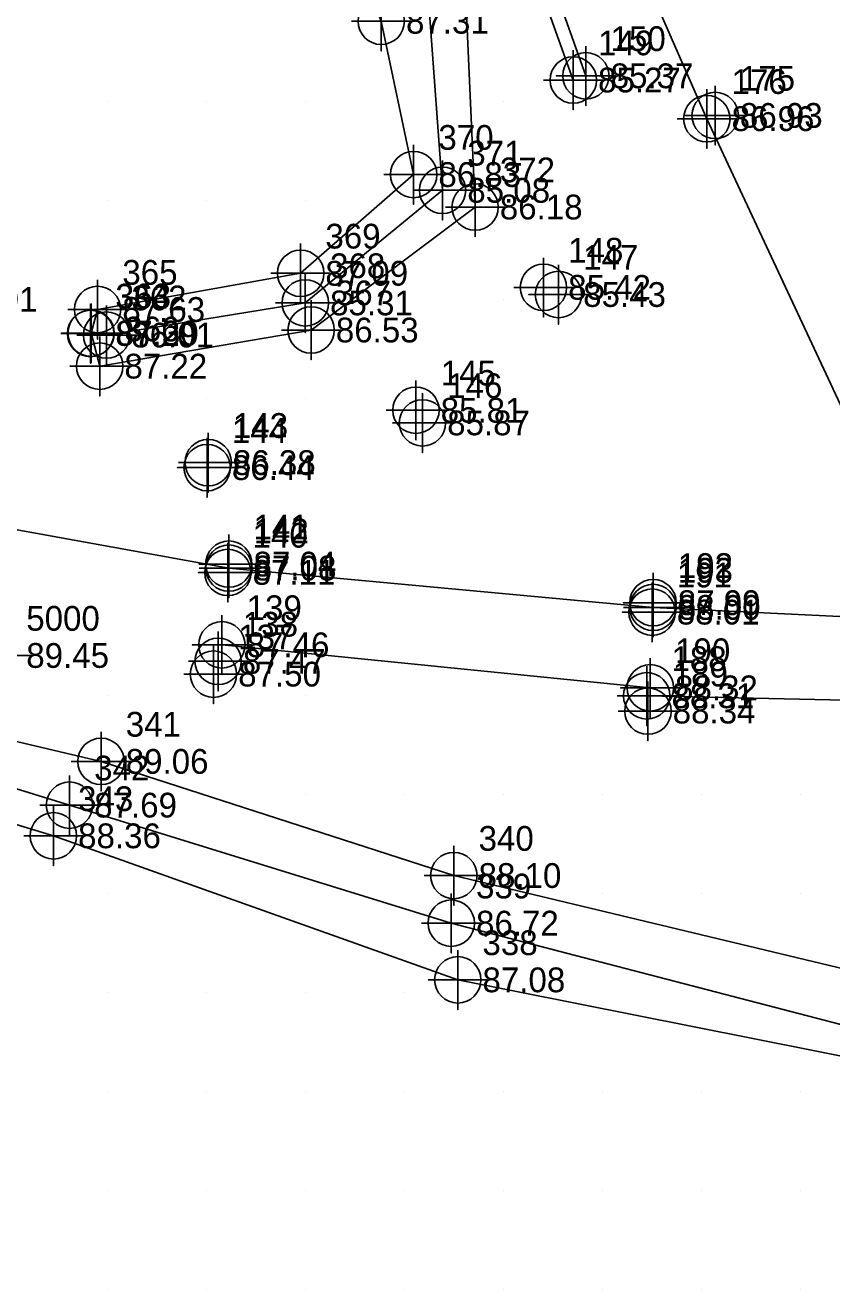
# Model space of a CAD drawing. Extents: x 1988140 to 1988766, y 249950 to 250250.
# Drawn here: x 1988211.7 to 1988293.2, y 249980 to 250107.7 of the extents above; entities that cross this region are included whole.
import ezdxf

# ---------------------------------------------------------------- set-up
doc = ezdxf.new("R2010")
doc.units = 0
for name, color, linetype in [('Exist DTM Breakline', 7, 'Continuous'), ('Exist DTM Breakline Cogo Elevation', 7, 'Continuous'), ('Exist DTM Breakline Cogo Number', 7, 'Continuous'), ('Exist DTM Breakline Cogo Point CELL', 7, 'Continuous'), ('Exist DTM Crownline', 7, 'Continuous'), ('Exist DTM Crownline Cogo Elevation', 7, 'Continuous'), ('Exist DTM Crownline Cogo Number', 7, 'Continuous'), ('Exist DTM Crownline Cogo Point CELL', 7, 'Continuous'), ('Exist DTM QL2 LIDAR Elevation Point', 7, 'Continuous'), ('Exist DTM Regular Point CELL', 7, 'Continuous'), ('Exist DTM Regular Point Cogo Elevation', 7, 'Continuous'), ('Exist DTM Regular Point Cogo Number', 7, 'Continuous'), ('Exist Roads EOP', 7, 'Continuous'), ('Exist Roads EOP Cogo Elevation', 7, 'Continuous'), ('Exist Roads EOP Cogo Number', 7, 'Continuous'), ('Exist Roads EOP Cogo Point CELL', 7, 'Continuous'), ('Exist Roads EOT', 7, 'Continuous'), ('Exist Roads EOT Cogo Elevation', 7, 'Continuous'), ('Exist Roads EOT Cogo Number', 7, 'Continuous'), ('Exist Roads EOT Cogo Point CELL', 7, 'Continuous')]:
    doc.layers.add(name, color=color, linetype=linetype)

msp = doc.modelspace()

# ---------------------------------------------------------------- linework, layer by layer
at = {"layer": 'Exist DTM Breakline'}
for points in [[(1988205.5595, 250223.4953), (1988232.1956, 250166.792), (1988256.1231, 250111.9343), (1988257.1237, 250089.3736), (1988240.5529, 250076.9489), (1988219.1842, 250073.2983), (1988218.3199, 250076.6342), (1988218.9736, 250079.0217)], [(1988219.8819, 250076.4392), (1988239.9643, 250079.6884), (1988253.8373, 250091.0619), (1988252.3677, 250110.8012), (1988229.9431, 250165.984), (1988203.3987, 250222.3896)], [(1988218.9736, 250079.0217), (1988239.4939, 250082.6807), (1988250.9135, 250092.6542), (1988247.6427, 250108.1384), (1988226.5384, 250163.725), (1988201.0735, 250219.7038)], [(1988182.6136, 250035.5158), (1988182.9813, 250039.2171), (1988184.903, 250041.4732), (1988219.3187, 250033.3718), (1988254.9783, 250021.8401), (1988300.1272, 250011.0374)], [(1988185.4236, 250038.4105), (1988216.1279, 250028.952), (1988254.719, 250017.0301), (1988298.2155, 250005.7241)], [(1988297.226, 250002.9987), (1988255.3705, 250011.301), (1988214.5049, 250025.8516), (1988182.6136, 250035.5158)]]:
    msp.add_lwpolyline(points, dxfattribs=at)
at = {"layer": 'Exist DTM Breakline Cogo Point CELL'}
for points in [[(1988247.6427, 250111.1384), (1988247.6427, 250105.1384), (1988247.6427, 250108.1384), (1988250.6427, 250108.1384), (1988244.6427, 250108.1384)], [(1988250.9135, 250095.6542), (1988250.9135, 250089.6542), (1988250.9135, 250092.6542), (1988253.9135, 250092.6542), (1988247.9135, 250092.6542)], [(1988253.8373, 250094.0619), (1988253.8373, 250088.0619), (1988253.8373, 250091.0619), (1988256.8373, 250091.0619), (1988250.8373, 250091.0619)], [(1988257.1237, 250092.3736), (1988257.1237, 250086.3736), (1988257.1237, 250089.3736), (1988260.1237, 250089.3736), (1988254.1237, 250089.3736)], [(1988239.4939, 250085.6807), (1988239.4939, 250079.6807), (1988239.4939, 250082.6807), (1988242.4939, 250082.6807), (1988236.4939, 250082.6807)], [(1988218.9736, 250082.0217), (1988218.9736, 250076.0217), (1988218.9736, 250079.0217), (1988221.9736, 250079.0217), (1988215.9736, 250079.0217)], [(1988239.9643, 250082.6884), (1988239.9643, 250076.6884), (1988239.9643, 250079.6884), (1988242.9643, 250079.6884), (1988236.9643, 250079.6884)], [(1988218.2676, 250079.6003), (1988218.2676, 250073.6003), (1988218.2676, 250076.6003), (1988221.2676, 250076.6003), (1988215.2676, 250076.6003)], [(1988218.3199, 250079.6342), (1988218.3199, 250073.6342), (1988218.3199, 250076.6342), (1988221.3199, 250076.6342), (1988215.3199, 250076.6342)], [(1988219.8819, 250079.4392), (1988219.8819, 250073.4392), (1988219.8819, 250076.4392), (1988222.8819, 250076.4392), (1988216.8819, 250076.4392)], [(1988240.5529, 250079.9489), (1988240.5529, 250073.9489), (1988240.5529, 250076.9489), (1988243.5529, 250076.9489), (1988237.5529, 250076.9489)], [(1988219.1842, 250076.2983), (1988219.1842, 250070.2983), (1988219.1842, 250073.2983), (1988222.1842, 250073.2983), (1988216.1842, 250073.2983)], [(1988219.3187, 250036.3718), (1988219.3187, 250030.3718), (1988219.3187, 250033.3718), (1988222.3187, 250033.3718), (1988216.3187, 250033.3718)], [(1988216.1279, 250031.952), (1988216.1279, 250025.952), (1988216.1279, 250028.952), (1988219.1279, 250028.952), (1988213.1279, 250028.952)], [(1988214.5049, 250028.8516), (1988214.5049, 250022.8516), (1988214.5049, 250025.8516), (1988217.5049, 250025.8516), (1988211.5049, 250025.8516)], [(1988254.9783, 250024.8401), (1988254.9783, 250018.8401), (1988254.9783, 250021.8401), (1988257.9783, 250021.8401), (1988251.9783, 250021.8401)], [(1988254.719, 250020.0301), (1988254.719, 250014.0301), (1988254.719, 250017.0301), (1988257.719, 250017.0301), (1988251.719, 250017.0301)], [(1988255.3705, 250014.301), (1988255.3705, 250008.301), (1988255.3705, 250011.301), (1988258.3705, 250011.301), (1988252.3705, 250011.301)]]:
    msp.add_lwpolyline(points, dxfattribs=at)
for centre in [(1988247.6427, 250108.1384), (1988250.9135, 250092.6542), (1988253.8373, 250091.0619), (1988257.1237, 250089.3736), (1988239.4939, 250082.6807), (1988239.9643, 250079.6884), (1988218.9736, 250079.0217), (1988218.2676, 250076.6003), (1988218.3199, 250076.6342), (1988219.8819, 250076.4392), (1988240.5529, 250076.9489), (1988219.1842, 250073.2983), (1988219.3187, 250033.3718), (1988216.1279, 250028.952), (1988214.5049, 250025.8516), (1988254.9783, 250021.8401), (1988254.719, 250017.0301), (1988255.3705, 250011.301)]:
    msp.add_circle(centre, 2.344, dxfattribs=at)
at = {"layer": 'Exist DTM Crownline'}
for p, q in [((1988196.8572, 250059.2912), (1988232.2445, 250052.8974)), ((1988232.2445, 250052.8974), (1988275.108, 250048.9258)), ((1988275.108, 250048.9258), (1988302.7374, 250047.561))]:
    msp.add_line(p, q, dxfattribs=at)
msp.add_lwpolyline([(1988218.8793, 250228.6049), (1988245.0113, 250174.1068), (1988268.5227, 250125.7119), (1988280.5459, 250098.297), (1988299.095, 250058.5693)], dxfattribs=at)
at = {"layer": 'Exist DTM Crownline Cogo Point CELL'}
for points in [[(1988280.5459, 250101.297), (1988280.5459, 250095.297), (1988280.5459, 250098.297), (1988283.5459, 250098.297), (1988277.5459, 250098.297)], [(1988232.2445, 250055.8974), (1988232.2445, 250049.8974), (1988232.2445, 250052.8974), (1988235.2445, 250052.8974), (1988229.2445, 250052.8974)], [(1988275.108, 250051.9258), (1988275.108, 250045.9258), (1988275.108, 250048.9258), (1988278.108, 250048.9258), (1988272.108, 250048.9258)]]:
    msp.add_lwpolyline(points, dxfattribs=at)
for centre in [(1988280.5459, 250098.297), (1988232.2445, 250052.8974), (1988275.108, 250048.9258)]:
    msp.add_circle(centre, 2.344, dxfattribs=at)
at = {"layer": 'Exist DTM QL2 LIDAR Elevation Point'}
for p, q in [((1988220, 250100), (1988220, 250100)), ((1988230, 250100), (1988230, 250100)), ((1988240, 250100), (1988240, 250100)), ((1988260, 250100), (1988260, 250100)), ((1988220, 250090), (1988220, 250090)), ((1988230, 250090), (1988230, 250090)), ((1988240, 250090), (1988240, 250090)), ((1988260, 250090), (1988260, 250090)), ((1988250, 250080), (1988250, 250080)), ((1988260, 250080), (1988260, 250080)), ((1988220, 250070), (1988220, 250070)), ((1988230, 250070), (1988230, 250070)), ((1988240, 250070), (1988240, 250070)), ((1988220, 250040), (1988220, 250040)), ((1988230, 250040), (1988230, 250040)), ((1988240, 250040), (1988240, 250040)), ((1988230, 250030), (1988230, 250030)), ((1988240, 250030), (1988240, 250030)), ((1988250, 250030), (1988250, 250030)), ((1988260, 250030), (1988260, 250030)), ((1988270, 250030), (1988270, 250030)), ((1988280, 250030), (1988280, 250030)), ((1988290, 250030), (1988290, 250030)), ((1988220, 250020), (1988220, 250020)), ((1988270, 250020), (1988270, 250020)), ((1988280, 250020), (1988280, 250020)), ((1988290, 250020), (1988290, 250020)), ((1988220, 250010), (1988220, 250010)), ((1988230, 250010), (1988230, 250010)), ((1988240, 250010), (1988240, 250010)), ((1988250, 250010), (1988250, 250010)), ((1988220, 250000), (1988220, 250000)), ((1988230, 250000), (1988230, 250000)), ((1988240, 250000), (1988240, 250000)), ((1988250, 250000), (1988250, 250000)), ((1988260, 250000), (1988260, 250000)), ((1988270, 250000), (1988270, 250000)), ((1988280, 250000), (1988280, 250000)), ((1988290, 250000), (1988290, 250000)), ((1988220, 249990), (1988220, 249990)), ((1988230, 249990), (1988230, 249990)), ((1988240, 249990), (1988240, 249990)), ((1988250, 249990), (1988250, 249990)), ((1988260, 249990), (1988260, 249990)), ((1988270, 249990), (1988270, 249990)), ((1988280, 249990), (1988280, 249990)), ((1988290, 249990), (1988290, 249990)), ((1988220, 249980), (1988220, 249980)), ((1988230, 249980), (1988230, 249980)), ((1988240, 249980), (1988240, 249980)), ((1988250, 249980), (1988250, 249980)), ((1988260, 249980), (1988260, 249980)), ((1988270, 249980), (1988270, 249980)), ((1988280, 249980), (1988280, 249980)), ((1988290, 249980), (1988290, 249980))]:
    msp.add_line(p, q, dxfattribs=at)
at = {"layer": 'Exist DTM Regular Point CELL'}
for points in [[(1988209.2644, 250047.0711), (1988209.2644, 250041.0711), (1988209.2644, 250044.0711), (1988212.2644, 250044.0711), (1988206.2644, 250044.0711)], [(1988230.6835, 250045.1866), (1988230.6835, 250039.1866), (1988230.6835, 250042.1866), (1988233.6835, 250042.1866), (1988227.6835, 250042.1866)], [(1988274.5936, 250041.4505), (1988274.5936, 250035.4505), (1988274.5936, 250038.4505), (1988277.5936, 250038.4505), (1988271.5936, 250038.4505)]]:
    msp.add_lwpolyline(points, dxfattribs=at)
for centre in [(1988230.6835, 250042.1866), (1988274.5936, 250038.4505)]:
    msp.add_circle(centre, 2.344, dxfattribs=at)
at = {"layer": 'Exist Roads EOP'}
msp.add_line((1988274.4694, 250039.9969), (1988302.1608, 250039.3839), dxfattribs=at)
for points in [[(1988267.05, 250102.2049), (1988260.261, 250121.1174), (1988236.2175, 250173.2246), (1988211.7209, 250223.9639)], [(1988230.1518, 250063.553), (1988230.1518, 250063.553)]]:
    msp.add_lwpolyline(points, dxfattribs=at)
at = {"layer": 'Exist Roads EOP Cogo Point CELL'}
for points in [[(1988267.05, 250105.2049), (1988267.05, 250099.2049), (1988267.05, 250102.2049), (1988270.05, 250102.2049), (1988264.05, 250102.2049)], [(1988264.0317, 250084.2577), (1988264.0317, 250078.2577), (1988264.0317, 250081.2577), (1988267.0317, 250081.2577), (1988261.0317, 250081.2577)], [(1988251.1478, 250071.8457), (1988251.1478, 250065.8457), (1988251.1478, 250068.8457), (1988254.1478, 250068.8457), (1988248.1478, 250068.8457)], [(1988230.1518, 250066.553), (1988230.1518, 250060.553), (1988230.1518, 250063.553), (1988233.1518, 250063.553), (1988227.1518, 250063.553)], [(1988231.1533, 250046.4796), (1988231.1533, 250040.4796), (1988231.1533, 250043.4796), (1988234.1533, 250043.4796), (1988228.1533, 250043.4796)], [(1988274.4694, 250042.9969), (1988274.4694, 250036.9969), (1988274.4694, 250039.9969), (1988277.4694, 250039.9969), (1988271.4694, 250039.9969)]]:
    msp.add_lwpolyline(points, dxfattribs=at)
for centre in [(1988267.05, 250102.2049), (1988264.0317, 250081.2577), (1988251.1478, 250068.8457), (1988230.1518, 250063.553), (1988231.1533, 250043.4796), (1988274.4694, 250039.9969)]:
    msp.add_circle(centre, 2.344, dxfattribs=at)
at = {"layer": 'Exist Roads EOT'}
msp.add_line((1988231.5356, 250045.1461), (1988274.8339, 250040.7991), dxfattribs=at)
for points in [[(1988212.6737, 250224.3863), (1988236.7216, 250173.5203), (1988261.5404, 250121.6566), (1988268.3223, 250102.6287)], [(1988281.3883, 250098.6265), (1988281.3883, 250098.6265)]]:
    msp.add_lwpolyline(points, dxfattribs=at)
at = {"layer": 'Exist Roads EOT Cogo Point CELL'}
for points in [[(1988268.3223, 250105.6287), (1988268.3223, 250099.6287), (1988268.3223, 250102.6287), (1988265.3223, 250102.6287), (1988271.3223, 250102.6287)], [(1988281.3883, 250101.6265), (1988281.3883, 250095.6265), (1988281.3883, 250098.6265), (1988278.3883, 250098.6265), (1988284.3883, 250098.6265)], [(1988265.5464, 250083.5356), (1988265.5464, 250077.5356), (1988265.5464, 250080.5356), (1988262.5464, 250080.5356), (1988268.5464, 250080.5356)], [(1988251.8041, 250070.5666), (1988251.8041, 250064.5666), (1988251.8041, 250067.5666), (1988248.8041, 250067.5666), (1988254.8041, 250067.5666)], [(1988230.046, 250066.0487), (1988230.046, 250060.0487), (1988230.046, 250063.0487), (1988227.046, 250063.0487), (1988233.046, 250063.0487)], [(1988232.1403, 250055.4636), (1988232.1403, 250049.4636), (1988232.1403, 250052.4636), (1988229.1403, 250052.4636), (1988235.1403, 250052.4636)], [(1988232.2286, 250056.302), (1988232.2286, 250050.302), (1988232.2286, 250053.302), (1988229.2286, 250053.302), (1988235.2286, 250053.302)], [(1988275.0087, 250051.4486), (1988275.0087, 250045.4486), (1988275.0087, 250048.4486), (1988272.0087, 250048.4486), (1988278.0087, 250048.4486)], [(1988275.1074, 250052.4045), (1988275.1074, 250046.4045), (1988275.1074, 250049.4045), (1988272.1074, 250049.4045), (1988278.1074, 250049.4045)], [(1988231.5356, 250048.1461), (1988231.5356, 250042.1461), (1988231.5356, 250045.1461), (1988228.5356, 250045.1461), (1988234.5356, 250045.1461)], [(1988274.8339, 250043.7991), (1988274.8339, 250037.7991), (1988274.8339, 250040.7991), (1988271.8339, 250040.7991), (1988277.8339, 250040.7991)]]:
    msp.add_lwpolyline(points, dxfattribs=at)
for centre in [(1988268.3223, 250102.6287), (1988281.3883, 250098.6265), (1988265.5464, 250080.5356), (1988251.8041, 250067.5666), (1988230.046, 250063.0487), (1988232.2286, 250053.302), (1988232.1403, 250052.4636), (1988275.1074, 250049.4045), (1988275.0087, 250048.4486), (1988231.5356, 250045.1461), (1988274.8339, 250040.7991)]:
    msp.add_circle(centre, 2.344, dxfattribs=at)

# ---------------------------------------------------------------- texts
at = {"layer": 'Exist DTM Breakline Cogo Elevation'}
for s, p in [('87.31', (1988250.1427, 250106.8884)), ('86.83', (1988253.4135, 250091.4042)), ('85.08', (1988256.3373, 250089.8119)), ('86.18', (1988259.6237, 250088.1236)), ('87.09', (1988241.9939, 250081.4307)), ('87.91', (1988204.5406, 250078.7998)), ('85.31', (1988242.4643, 250078.4384)), ('87.63', (1988221.4736, 250077.7717)), ('86.53', (1988243.0529, 250075.6989)), ('87.29', (1988220.7676, 250075.3503)), ('87.30', (1988220.8199, 250075.3842)), ('86.01', (1988222.3819, 250075.1892)), ('87.22', (1988221.6842, 250072.0483)), ('89.06', (1988221.8187, 250032.1218)), ('87.69', (1988218.6279, 250027.702)), ('88.36', (1988217.0049, 250024.6016)), ('88.10', (1988257.4783, 250020.5901)), ('86.72', (1988257.219, 250015.7801)), ('87.08', (1988257.8705, 250010.051))]:
    msp.add_text(s, height=2.5, dxfattribs=at).set_placement(p)
at = {"layer": 'Exist DTM Breakline Cogo Number'}
for s, p in [('370', (1988253.4135, 250095.1542)), ('371', (1988256.3373, 250093.5619)), ('372', (1988259.6237, 250091.8736)), ('369', (1988241.9939, 250085.1807)), ('368', (1988242.4643, 250082.1884)), ('365', (1988221.4736, 250081.5217)), ('367', (1988243.0529, 250079.4489)), ('364', (1988220.7676, 250079.1003)), ('363', (1988220.8199, 250079.1342)), ('362', (1988222.3819, 250078.9392)), ('366', (1988221.6842, 250075.7983)), ('341', (1988221.8187, 250035.8718)), ('342', (1988218.6279, 250031.452)), ('343', (1988217.0049, 250028.3516)), ('340', (1988257.4783, 250024.3401)), ('339', (1988257.219, 250019.5301)), ('338', (1988257.8705, 250013.801))]:
    msp.add_text(s, height=2.5, dxfattribs=at).set_placement(p)
at = {"layer": 'Exist DTM Crownline Cogo Elevation'}
for s, p in [('86.96', (1988283.0459, 250097.047)), ('87.08', (1988234.7445, 250051.6474)), ('88.00', (1988277.608, 250047.6758))]:
    msp.add_text(s, height=2.5, dxfattribs=at).set_placement(p)
at = {"layer": 'Exist DTM Crownline Cogo Number'}
for s, p in [('176', (1988283.0459, 250100.797)), ('142', (1988234.7445, 250055.3974)), ('193', (1988277.608, 250051.4258))]:
    msp.add_text(s, height=2.5, dxfattribs=at).set_placement(p)
at = {"layer": 'Exist DTM Regular Point Cogo Elevation'}
for s, p in [('89.45', (1988211.7644, 250042.8211)), ('87.50', (1988233.1835, 250040.9366)), ('88.34', (1988277.0936, 250037.2005))]:
    msp.add_text(s, height=2.5, dxfattribs=at).set_placement(p)
at = {"layer": 'Exist DTM Regular Point Cogo Number'}
for s, p in [('5000', (1988211.7644, 250046.5711)), ('137', (1988233.1835, 250044.6866)), ('189', (1988277.0936, 250040.9505))]:
    msp.add_text(s, height=2.5, dxfattribs=at).set_placement(p)
at = {"layer": 'Exist Roads EOP Cogo Elevation'}
for s, p in [('85.27', (1988269.55, 250100.9549)), ('85.42', (1988266.5317, 250080.0077)), ('85.81', (1988253.6478, 250067.5957)), ('86.38', (1988232.6518, 250062.303)), ('87.47', (1988233.6533, 250042.2296)), ('88.31', (1988276.9694, 250038.7469))]:
    msp.add_text(s, height=2.5, dxfattribs=at).set_placement(p)
at = {"layer": 'Exist Roads EOP Cogo Number'}
for s, p in [('149', (1988269.55, 250104.7049)), ('148', (1988266.5317, 250083.7577)), ('145', (1988253.6478, 250071.3457)), ('143', (1988232.6518, 250066.053)), ('138', (1988233.6533, 250045.9796)), ('188', (1988276.9694, 250042.4969))]:
    msp.add_text(s, height=2.5, dxfattribs=at).set_placement(p)
at = {"layer": 'Exist Roads EOT Cogo Elevation'}
for s, p in [('85.37', (1988270.8223, 250101.3787)), ('86.93', (1988283.8883, 250097.3765)), ('85.43', (1988268.0464, 250079.2856)), ('85.87', (1988254.3041, 250066.3166)), ('86.44', (1988232.546, 250061.7987)), ('87.04', (1988234.7286, 250052.052)), ('87.11', (1988234.6403, 250051.2136)), ('87.99', (1988277.6074, 250048.1545)), ('88.01', (1988277.5087, 250047.1986)), ('87.46', (1988234.0356, 250043.8961)), ('88.32', (1988277.3339, 250039.5491))]:
    msp.add_text(s, height=2.5, dxfattribs=at).set_placement(p)
at = {"layer": 'Exist Roads EOT Cogo Number'}
for s, p in [('150', (1988270.8223, 250105.1287)), ('175', (1988283.8883, 250101.1265)), ('147', (1988268.0464, 250083.0356)), ('146', (1988254.3041, 250070.0666)), ('144', (1988232.546, 250065.5487)), ('141', (1988234.7286, 250055.802)), ('140', (1988234.6403, 250054.9636)), ('192', (1988277.6074, 250051.9045)), ('191', (1988277.5087, 250050.9486)), ('139', (1988234.0356, 250047.6461)), ('190', (1988277.3339, 250043.2991))]:
    msp.add_text(s, height=2.5, dxfattribs=at).set_placement(p)

doc.saveas('drawing.dxf')
